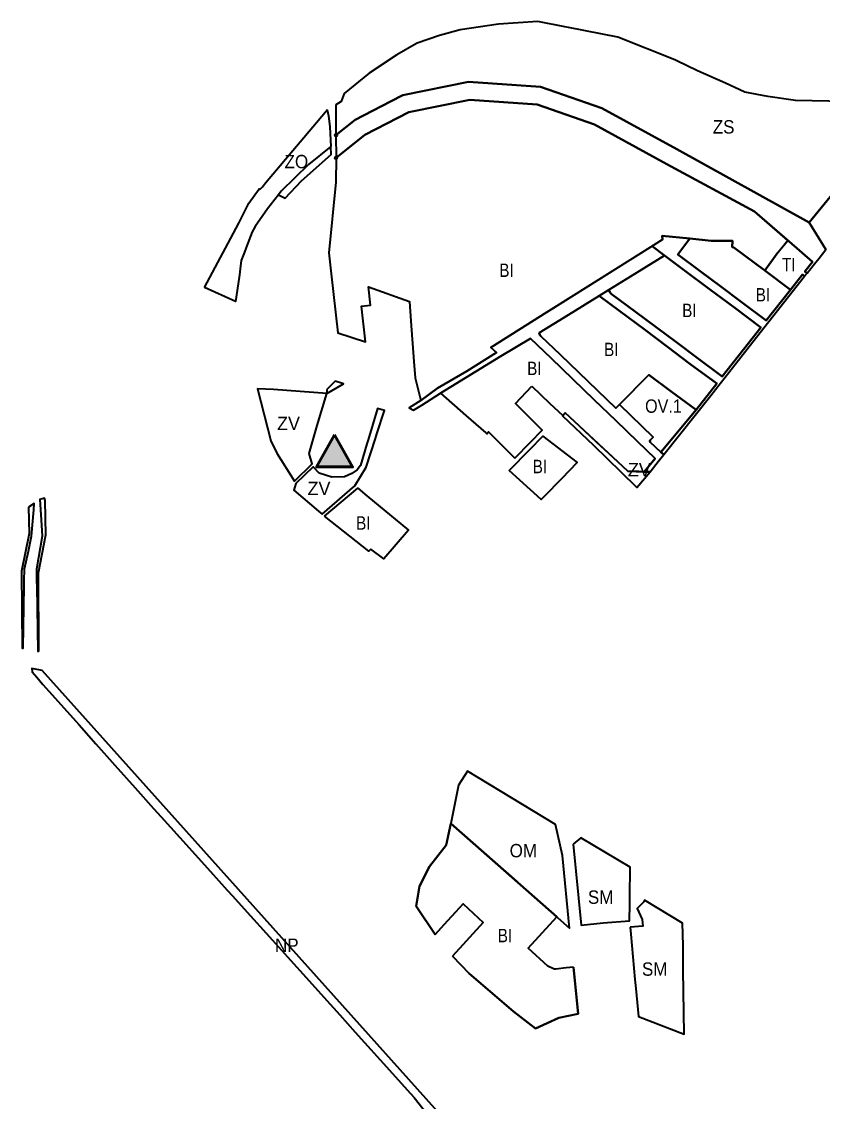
# Model space of a CAD drawing. Extents: x -650276 to -642489, y -1074311 to -1066658.
# Drawn here: x -650276 to -649558, y -1070272 to -1069304 of the extents above; entities that cross this region are included whole.
import ezdxf

# ---------------------------------------------------------------- set-up
doc = ezdxf.new("R2010")
doc.units = 0
doc.header["$LTSCALE"] = 4.8
doc.header["$PDMODE"] = 32
doc.header["$PDSIZE"] = 2.4
for name, color, linetype, lineweight in [('11', 7, 'Continuous', 35), ('12', 7, 'Continuous', 35), ('15', 7, 'Continuous', 35), ('18', 7, 'Continuous', 35), ('2', 7, 'Continuous', 35), ('30', 7, 'Continuous', 35), ('40', 7, 'Continuous', 35), ('41', 7, 'Continuous', 35), ('42', 7, 'Continuous', 35), ('48', 7, 'Continuous', 35), ('55', 7, 'Continuous', 53)]:
    doc.layers.add(name, color=color, linetype=linetype, lineweight=lineweight)
doc.layers.add('62', color=7, linetype='Continuous')
doc.layers.add('63', color=7, linetype='Continuous')

msp = doc.modelspace()

# ---------------------------------------------------------------- hatches: boundary and pattern name
at = {"layer": '55'}
msp.add_hatch(color=256, dxfattribs=at).paths.add_polyline_path([(-649995.793, -1069674.354), (-650011.744, -1069703), (-649979.36, -1069703)])

# ---------------------------------------------------------------- linework, layer by layer
at = {"layer": '11'}
msp.add_lwpolyline([(-649713.73, -1069620.32), (-649713.73, -1069620.32), (-649740.23, -1069647.14), (-649709.94, -1069676.28), (-649712.54, -1069678.98), (-649712.89, -1069679.87), (-649712.51, -1069680.75), (-649703.15, -1069689.75), (-649671.39, -1069651.93), (-649693.63, -1069635.33)], close=True, dxfattribs=at)
at = {"layer": '12'}
msp.add_lwpolyline([(-649891.21, -1070022.68), (-649832.007, -1070074.751), (-649784.87, -1070116.76), (-649791.31, -1070051.51), (-649797.45, -1070023.77), (-649876.31, -1069975.93), (-649884.59, -1069988.57)], close=True, dxfattribs=at)
at = {"layer": '15'}
for points in [[(-649561.17, -1069515.83), (-649555.16, -1069508.07), (-649570.03, -1069483.83), (-649688.625, -1069418.156), (-649755.971, -1069381.179), (-649810.846, -1069362.154), (-649875.434, -1069357.751), (-649934.363, -1069369.537), (-649945.397, -1069375.277), (-649977.239, -1069391.714), (-649994.329, -1069405.451)], [(-649994.293, -1069425.949), (-649968.465, -1069405.189), (-649929.015, -1069384.784), (-649874.391, -1069373.859)], [(-649874.391, -1069373.859), (-649814.067, -1069377.972), (-649762.488, -1069395.854), (-649697.525, -1069431.522), (-649619, -1069474), (-649588, -1069501)], [(-649994.329, -1069405.451), (-649994.329, -1069405.451), (-649994.293, -1069425.949), (-649994.293, -1069425.949)], [(-649710.957, -1069505.107), (-649801.49, -1069561.98), (-649805.22, -1069564.32), (-649855.34, -1069595.8), (-649850.24, -1069600.295), (-649877.129, -1069617.006), (-649903.292, -1069632.541), (-649918.35, -1069643.45), (-649928.67, -1069649.89), (-649924.8, -1069652.19), (-649920.45, -1069649.53), (-649917.38, -1069647.56), (-649900.64, -1069636.78), (-649846.38, -1069603.8), (-649820.02, -1069587.73), (-649801.48, -1069605.57), (-649782.03, -1069624.28), (-649762.85, -1069642.73), (-649743.41, -1069661.43), (-649723.97, -1069680.13), (-649707.985, -1069695.508), (-649717.884, -1069707.295), (-649712.64, -1069707.43), (-649705.28, -1069698.11), (-649700.42, -1069691.8), (-649703.15, -1069689.75), (-649712.51, -1069680.75), (-649712.89, -1069679.87), (-649712.54, -1069678.98), (-649709.94, -1069676.28), (-649740.23, -1069647.14), (-649743.39, -1069650.35), (-649759.97, -1069634.4), (-649776.54, -1069618.46), (-649793.12, -1069602.51), (-649810.49, -1069585.81), (-649811.52, -1069584.44), (-649812.08, -1069582.83)], [(-649722.6, -1069527.61), (-649699.72, -1069513.5), (-649710.957, -1069505.107)], [(-649588, -1069501), (-649567, -1069519), (-649573.922, -1069527.657), (-649571.94, -1069529.24), (-649565.33, -1069521.01), (-649561.17, -1069515.83)], [(-649812.08, -1069582.83), (-649785.72, -1069566.56), (-649758.29, -1069549.64), (-649749.62, -1069544.29), (-649722.6, -1069527.61)]]:
    msp.add_lwpolyline(points, dxfattribs=at)
for points in [[(-650025.31, -1069446.49), (-649998.512, -1069422.926), (-649999.01, -1069415.628), (-650018.873, -1069431.749), (-650043.521, -1069455.69), (-650045.72, -1069459.1), (-650040.012, -1069461.999)], [(-649677.124, -1069610.681), (-649652.88, -1069628.36), (-649671.39, -1069651.93), (-649703.15, -1069689.75), (-649700.42, -1069691.8), (-649658.13, -1069638.84), (-649651.846, -1069630.82), (-649641.978, -1069618.226), (-649620.45, -1069590.75), (-649574.1, -1069531.97), (-649576.071, -1069530.398), (-649586.82, -1069544.11), (-649608.44, -1069571.69), (-649630.88, -1069554.92), (-649649.31, -1069541.16), (-649667.74, -1069527.4), (-649687.77, -1069512.44), (-649677.02, -1069498.32), (-649701.7, -1069495.89), (-649701.57, -1069499.21), (-649710.957, -1069505.107), (-649699.72, -1069513.5), (-649681.7, -1069526.96), (-649659.26, -1069543.71), (-649636.83, -1069560.47), (-649613.37, -1069577.98), (-649628.8, -1069597.67), (-649647.93, -1069622.07), (-649670.34, -1069605.34), (-649688.76, -1069591.57), (-649707.19, -1069577.81), (-649725.62, -1069564.05), (-649747.5, -1069547.71), (-649748.89, -1069546.2), (-649749.62, -1069544.29), (-649758.29, -1069549.64), (-649739.75, -1069563.48), (-649718.13, -1069579.63), (-649696.91, -1069595.47)], [(-650002.39, -1069633.65), (-650002.65, -1069637.14), (-649987.49, -1069628.6), (-649994.913, -1069626.246)]]:
    msp.add_lwpolyline(points, close=True, dxfattribs=at)
for p in [(-649994.329, -1069405.451), (-649994.293, -1069425.949)]:
    msp.add_point(p, dxfattribs=at)
at = {"layer": '18'}
for points in [[(-649781.53, -1070041.2), (-649774.45, -1070113.92), (-649754.82, -1070111.89), (-649731.12, -1070109.96), (-649730.96, -1070094.91), (-649730.89, -1070088.96), (-649730.6, -1070061.98), (-649774.73, -1070035.58)], [(-649730.57, -1070115.76), (-649730, -1070122.01), (-649726.22, -1070162.75), (-649725.49, -1070170.64), (-649723.17, -1070195.81), (-649682.04, -1070211.58), (-649683.12, -1070154.14), (-649682.98, -1070132.1), (-649683.57, -1070112.05), (-649717.72, -1070091.61), (-649718.71, -1070093.35), (-649724.36, -1070099.03), (-649719.69, -1070108.94), (-649719.24, -1070114.87)]]:
    msp.add_lwpolyline(points, close=True, dxfattribs=at)
at = {"layer": '2'}
for points in [[(-649639.18, -1069505.96), (-649637.69, -1069506.15), (-649628.36, -1069513.11), (-649609.93, -1069526.87), (-649598.004, -1069510.814), (-649589.257, -1069499.905), (-649619, -1069474), (-649697.525, -1069431.522), (-649762.488, -1069395.854), (-649814.067, -1069377.972), (-649874.391, -1069373.859), (-649929.015, -1069384.784), (-649968.465, -1069405.189), (-649994.293, -1069425.949), (-649994.53, -1069447.61), (-650000.59, -1069511.15), (-649998.81, -1069527.07), (-649998.5, -1069529.88), (-649992.59, -1069582.88), (-649967.81, -1069590.74), (-649971.38, -1069558.79), (-649963.43, -1069557.91), (-649965.26, -1069541.51), (-649928.48, -1069554.57), (-649927.3, -1069572.44)], [(-649927.3, -1069572.44), (-649924.62, -1069608.53), (-649923.17, -1069623.14), (-649918.35, -1069643.45), (-649918.35, -1069643.45), (-649903.292, -1069632.541), (-649877.129, -1069617.006), (-649850.24, -1069600.295), (-649855.34, -1069595.8), (-649805.22, -1069564.32), (-649801.49, -1069561.98), (-649701.57, -1069499.21), (-649701.7, -1069495.89), (-649677.02, -1069498.32), (-649658.01, -1069500.19), (-649647.45, -1069500.23), (-649638.81, -1069500.26), (-649639.18, -1069505.96)], [(-649677.02, -1069498.32), (-649687.77, -1069512.44), (-649667.74, -1069527.4), (-649649.31, -1069541.16)], [(-649639.18, -1069505.96), (-649638.81, -1069500.26), (-649647.45, -1069500.23), (-649658.01, -1069500.19), (-649677.02, -1069498.32)], [(-649609.93, -1069526.87), (-649628.36, -1069513.11), (-649637.69, -1069506.15), (-649639.18, -1069505.96)], [(-649707.19, -1069577.81), (-649688.76, -1069591.57), (-649670.34, -1069605.34), (-649647.93, -1069622.07), (-649628.8, -1069597.67), (-649613.37, -1069577.98), (-649636.83, -1069560.47), (-649659.26, -1069543.71), (-649681.7, -1069526.96), (-649699.72, -1069513.5), (-649722.6, -1069527.61), (-649749.62, -1069544.29)], [(-649649.31, -1069541.16), (-649630.88, -1069554.92), (-649608.44, -1069571.69), (-649586.82, -1069544.11), (-649609.93, -1069526.87)], [(-649749.62, -1069544.29), (-649748.89, -1069546.2), (-649747.5, -1069547.71), (-649725.62, -1069564.05), (-649707.19, -1069577.81)], [(-649758.29, -1069549.64), (-649785.72, -1069566.56), (-649812.08, -1069582.83)], [(-649671.39, -1069651.93), (-649652.88, -1069628.36), (-649677.124, -1069610.681), (-649696.91, -1069595.47), (-649718.13, -1069579.63), (-649739.75, -1069563.48), (-649758.29, -1069549.64)], [(-649812.08, -1069582.83), (-649811.52, -1069584.44), (-649810.49, -1069585.81), (-649793.12, -1069602.51), (-649776.54, -1069618.46), (-649759.97, -1069634.4)], [(-649788.91, -1069654.4), (-649781.09, -1069661.69), (-649761.34, -1069680.08), (-649741.61, -1069698.46), (-649732.52, -1069706.92), (-649717.884, -1069707.295), (-649707.985, -1069695.508), (-649723.97, -1069680.13), (-649743.41, -1069661.43), (-649762.85, -1069642.73), (-649782.03, -1069624.28), (-649801.48, -1069605.57), (-649820.02, -1069587.73), (-649846.38, -1069603.8), (-649900.64, -1069636.78)], [(-649740.23, -1069647.14), (-649713.73, -1069620.32), (-649713.73, -1069620.32), (-649693.63, -1069635.33), (-649671.39, -1069651.93)], [(-649833.94, -1069695.239), (-649819.98, -1069680.92), (-649809.47, -1069670.13), (-649833.38, -1069646.08), (-649818.71, -1069630.64)], [(-649818.71, -1069630.64), (-649802.9, -1069645.96), (-649791, -1069657), (-649788.91, -1069654.4)], [(-649759.97, -1069634.4), (-649743.39, -1069650.35), (-649740.23, -1069647.14)], [(-649900.64, -1069636.78), (-649877.82, -1069656.83), (-649859.96, -1069672.53)], [(-649859.96, -1069672.53), (-649859.17, -1069673.22), (-649857.49, -1069671.46), (-649833.94, -1069695.239)], [(-649905.51, -1070122.35), (-649922.3, -1070096.9), (-649919.55, -1070079.01), (-649910.34, -1070061.29), (-649895.45, -1070042.15), (-649891.21, -1070022.68), (-649796.4, -1070106.56)], [(-649796.4, -1070106.56), (-649891.21, -1070022.68), (-649895.45, -1070042.15), (-649910.34, -1070061.29), (-649919.55, -1070079.01), (-649922.3, -1070096.9), (-649905.51, -1070122.35)], [(-649894.095, -1070109.853), (-649886.83, -1070101.89), (-649880.42, -1070094.87), (-649862.22, -1070111.54), (-649889.87, -1070141.83)], [(-649905.51, -1070122.35), (-649897.03, -1070113.07), (-649894.095, -1070109.853)], [(-649804.29, -1070150.68), (-649821.97, -1070134.58), (-649796.4, -1070106.56)], [(-649781.433, -1070151.59), (-649777.29, -1070193.57), (-649794.37, -1070197.2), (-649815.33, -1070206.63), (-649835.28, -1070191.27), (-649874.94, -1070157.19), (-649889.87, -1070141.83)], [(-649889.87, -1070141.83), (-649874.94, -1070157.19), (-649835.28, -1070191.27), (-649815.33, -1070206.63), (-649794.37, -1070197.2)], [(-649781.436, -1070151.591), (-649787.92, -1070152.23), (-649797.33, -1070153.41), (-649798.33, -1070153.32), (-649799.29, -1070153), (-649804.29, -1070150.68)], [(-649794.37, -1070197.2), (-649777.29, -1070193.57), (-649781.433, -1070151.59)]]:
    msp.add_lwpolyline(points, dxfattribs=at)
for points in [[(-649838.99, -1069706.15), (-649820.64, -1069687.33), (-649808.96, -1069675.34), (-649777.94, -1069699.2), (-649792.13, -1069713.65), (-649807.66, -1069729.46), (-649810.41, -1069732.28), (-649819.9, -1069723.61)], [(-650004.59, -1069747.27), (-649974.86, -1069721.96), (-649966.52, -1069728.87), (-649929.38, -1069759.65), (-649951.56, -1069785.42), (-649963, -1069776.7), (-649965, -1069778.7)]]:
    msp.add_lwpolyline(points, close=True, dxfattribs=at)
at = {"layer": '30'}
for points in [[(-649571.94, -1069529.24), (-649573.922, -1069527.657), (-649567, -1069519), (-649588, -1069501), (-649589.257, -1069499.905), (-649597.935, -1069510.728)], [(-649597.997, -1069510.805), (-649598.004, -1069510.814), (-649609.93, -1069526.87), (-649586.82, -1069544.11)], [(-649597.935, -1069510.728), (-649597.763, -1069510.865), (-649597.997, -1069510.805)], [(-649586.82, -1069544.11), (-649576.071, -1069530.398), (-649574.1, -1069531.97), (-649571.94, -1069529.24)]]:
    msp.add_lwpolyline(points, dxfattribs=at)
at = {"layer": '40'}
for points in [[(-650002.65, -1069637.14), (-650050.26, -1069633.65), (-650064.77, -1069633.06), (-650052.88, -1069679.49), (-650047.45, -1069690.69), (-650031.64, -1069715.9), (-650015.53, -1069700.21), (-650018.31, -1069690.89), (-650011.15, -1069665.82)], [(-649998, -1069712.26), (-650009.509, -1069708.678), (-650014.74, -1069702.9), (-650030.26, -1069717.96), (-650032.13, -1069723.75), (-650010.04, -1069742.58), (-650006.85, -1069745.3), (-649977.31, -1069720.05), (-649967.27, -1069703.29), (-649958.87, -1069677.59), (-649957.54, -1069673.5), (-649950.69, -1069652.54), (-649957.15, -1069650.76), (-649965.45, -1069678.6), (-649966.59, -1069682.44), (-649972.35, -1069701.78), (-649975.45, -1069705.65), (-649980.22, -1069709.07), (-649986.69, -1069712.03)], [(-649738.93, -1069707.42), (-649724.51, -1069721.57), (-649712.64, -1069707.43), (-649732.52, -1069706.92), (-649741.61, -1069698.46), (-649788.91, -1069654.4), (-649791.3, -1069657.21), (-649763.31, -1069683.5)]]:
    msp.add_lwpolyline(points, close=True, dxfattribs=at)
at = {"layer": '41'}
msp.add_lwpolyline([(-649537.32, -1069375.23), (-649582.25, -1069374.51), (-649607.18, -1069370.92), (-649627.76, -1069366.8), (-649645.03, -1069358.8), (-649670.23, -1069347.9), (-649688.73, -1069338.7), (-649690.59, -1069337.98), (-649741.5, -1069317.74), (-649785.8, -1069308.94), (-649789, -1069308.31), (-649813.3, -1069303.66), (-649848.62, -1069305.95), (-649882.93, -1069311.1), (-649901.58, -1069316.01), (-649921.54, -1069323.03), (-649922.11, -1069323.35), (-649939.81, -1069333.47), (-649964.53, -1069350.02), (-649987.12, -1069368.03), (-649989.67, -1069375.36), (-649994.38, -1069378.33), (-649994.35, -1069394.43), (-649994.34, -1069398.8), (-649994.329, -1069405.451), (-649977.239, -1069391.714), (-649945.397, -1069375.277), (-649934.363, -1069369.537), (-649875.434, -1069357.751), (-649810.846, -1069362.154), (-649755.971, -1069381.179), (-649688.625, -1069418.156), (-649570.03, -1069483.83), (-649499.761, -1069397.905)], dxfattribs=at)
at = {"layer": '42'}
msp.add_lwpolyline([(-650112.18, -1069542.11), (-650081.29, -1069484.35), (-650072.5, -1069466.44), (-650063.12, -1069453.54), (-650062.17, -1069454.05), (-650060.29, -1069451.7), (-650057.49, -1069448.18), (-650026.33, -1069411.47), (-650003.73, -1069384.71), (-650002.11, -1069382.8), (-650001.13, -1069388.13), (-649999.95, -1069397.98), (-649999.01, -1069415.628), (-650018.873, -1069431.749), (-650043.521, -1069455.69), (-650045.72, -1069459.1), (-650055.612, -1069471.639), (-650066.897, -1069487.541), (-650069.369, -1069492.132), (-650074.75, -1069506.133), (-650076.365, -1069510.333), (-650079.264, -1069517.874), (-650080.302, -1069525.418), (-650080.802, -1069530.768), (-650082.963, -1069544.736), (-650084.345, -1069554.773)], close=True, dxfattribs=at)
at = {"layer": '48'}
for points in [[(-649499.761, -1069397.905), (-649570.03, -1069483.83), (-649555.16, -1069508.07)], [(-649843.513, -1070347.685), (-650257.713, -1069885.547), (-650266.89, -1069883.7), (-650266.68, -1069886.78), (-650262.64, -1069891.57), (-650257.16, -1069898.07), (-650224.71, -1069934.41), (-650209.51, -1069951.43), (-650192.51, -1069970.47), (-650174.3, -1069990.86), (-650157.87, -1070009.26), (-650151.03, -1070016.84), (-650134.26, -1070035.45), (-650106.76, -1070065.96), (-650091.89, -1070082.46), (-650087.18, -1070087.68), (-650076.72, -1070099.29), (-650051.33, -1070127.45), (-650037.78, -1070142.48), (-650018.41, -1070163.97), (-650005.3, -1070178.51), (-649990.95, -1070194.43), (-649977.05, -1070209.85), (-649946.39, -1070243.87), (-649930.46, -1070261.54), (-649924.15, -1070268.55), (-649913.03, -1070282.44)]]:
    msp.add_lwpolyline(points, dxfattribs=at)
for points in [[(-650260.645, -1069868.536), (-650260.748, -1069867.327), (-650261.204, -1069797.969), (-650254.411, -1069764.006), (-650255.21, -1069733.253), (-650255.716, -1069731.162), (-650259.97, -1069732.29), (-650258.74, -1069750.62), (-650257.77, -1069765.2), (-650262.93, -1069794.84), (-650262.77, -1069805.54), (-650262.7, -1069809.89), (-650261.8, -1069868.33)], [(-650270.059, -1069739.232), (-650269.449, -1069762.714), (-650276.214, -1069796.532), (-650275.76, -1069865.474), (-650274.95, -1069865.62), (-650273.87, -1069809.74), (-650273.78, -1069805.2), (-650273.58, -1069794.48), (-650270.15, -1069778.65), (-650267.22, -1069765.1), (-650265.37, -1069741.61), (-650264.91, -1069735.69)]]:
    msp.add_lwpolyline(points, close=True, dxfattribs=at)
at = {"layer": '55'}
msp.add_lwpolyline([(-649995.793, -1069674.354), (-650011.744, -1069703), (-649979.36, -1069703)], close=True, dxfattribs=at)

# ---------------------------------------------------------------- texts
at = {"layer": '62'}
for s, width, p in [('ZS', 0.95, (-649656.482, -1069404.05)), ('ZO', 0.95, (-650040.423, -1069435.188)), ('BI', 0.85, (-649847.88, -1069532.658)), ('BI', 0.85, (-649817.88, -1069708.658)), ('BI', 0.85, (-649976.221, -1069759.292)), ('OM', 0.95, (-649838.604, -1070053.132)), ('SM', 0.95, (-649768.411, -1070094.846)), ('BI', 0.85, (-649849.221, -1070129.292)), ('NP', 0.95, (-650048.985, -1070137.967)), ('SM', 0.95, (-649719.964, -1070159.337))]:
    msp.add_text(s, height=12, dxfattribs=dict(at, width=width)).set_placement(p)
for p in [(-650047.124, -1069669.988), (-650019.82, -1069728.32)]:
    msp.add_text('ZV', height=12, dxfattribs=at).set_placement(p)
at = {"layer": '63'}
for s, width, p in [('TI', 0.85, (-649594.476, -1069527.535)), ('BI', 0.85, (-649617.88, -1069554.658)), ('BI', 0.85, (-649683.88, -1069568.658)), ('BI', 0.85, (-649753.88, -1069603.658)), ('BI', 0.85, (-649822.88, -1069620.658)), ('OV.1', 0.9, (-649717.147, -1069654.487))]:
    msp.add_text(s, height=12, dxfattribs=dict(at, width=width)).set_placement(p)
msp.add_text('ZV', height=12, dxfattribs=at).set_placement((-649732.572, -1069711.498))

doc.saveas('drawing.dxf')
